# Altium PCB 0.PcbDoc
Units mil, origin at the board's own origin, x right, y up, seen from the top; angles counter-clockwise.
Board outline 2362.2 x 1889.76 mil, 2 copper layers (Top Layer, Bottom Layer); 26 components, 34 nets, 135 pads, 53 vias.
Unrouted connection lines stored in the file: 52.
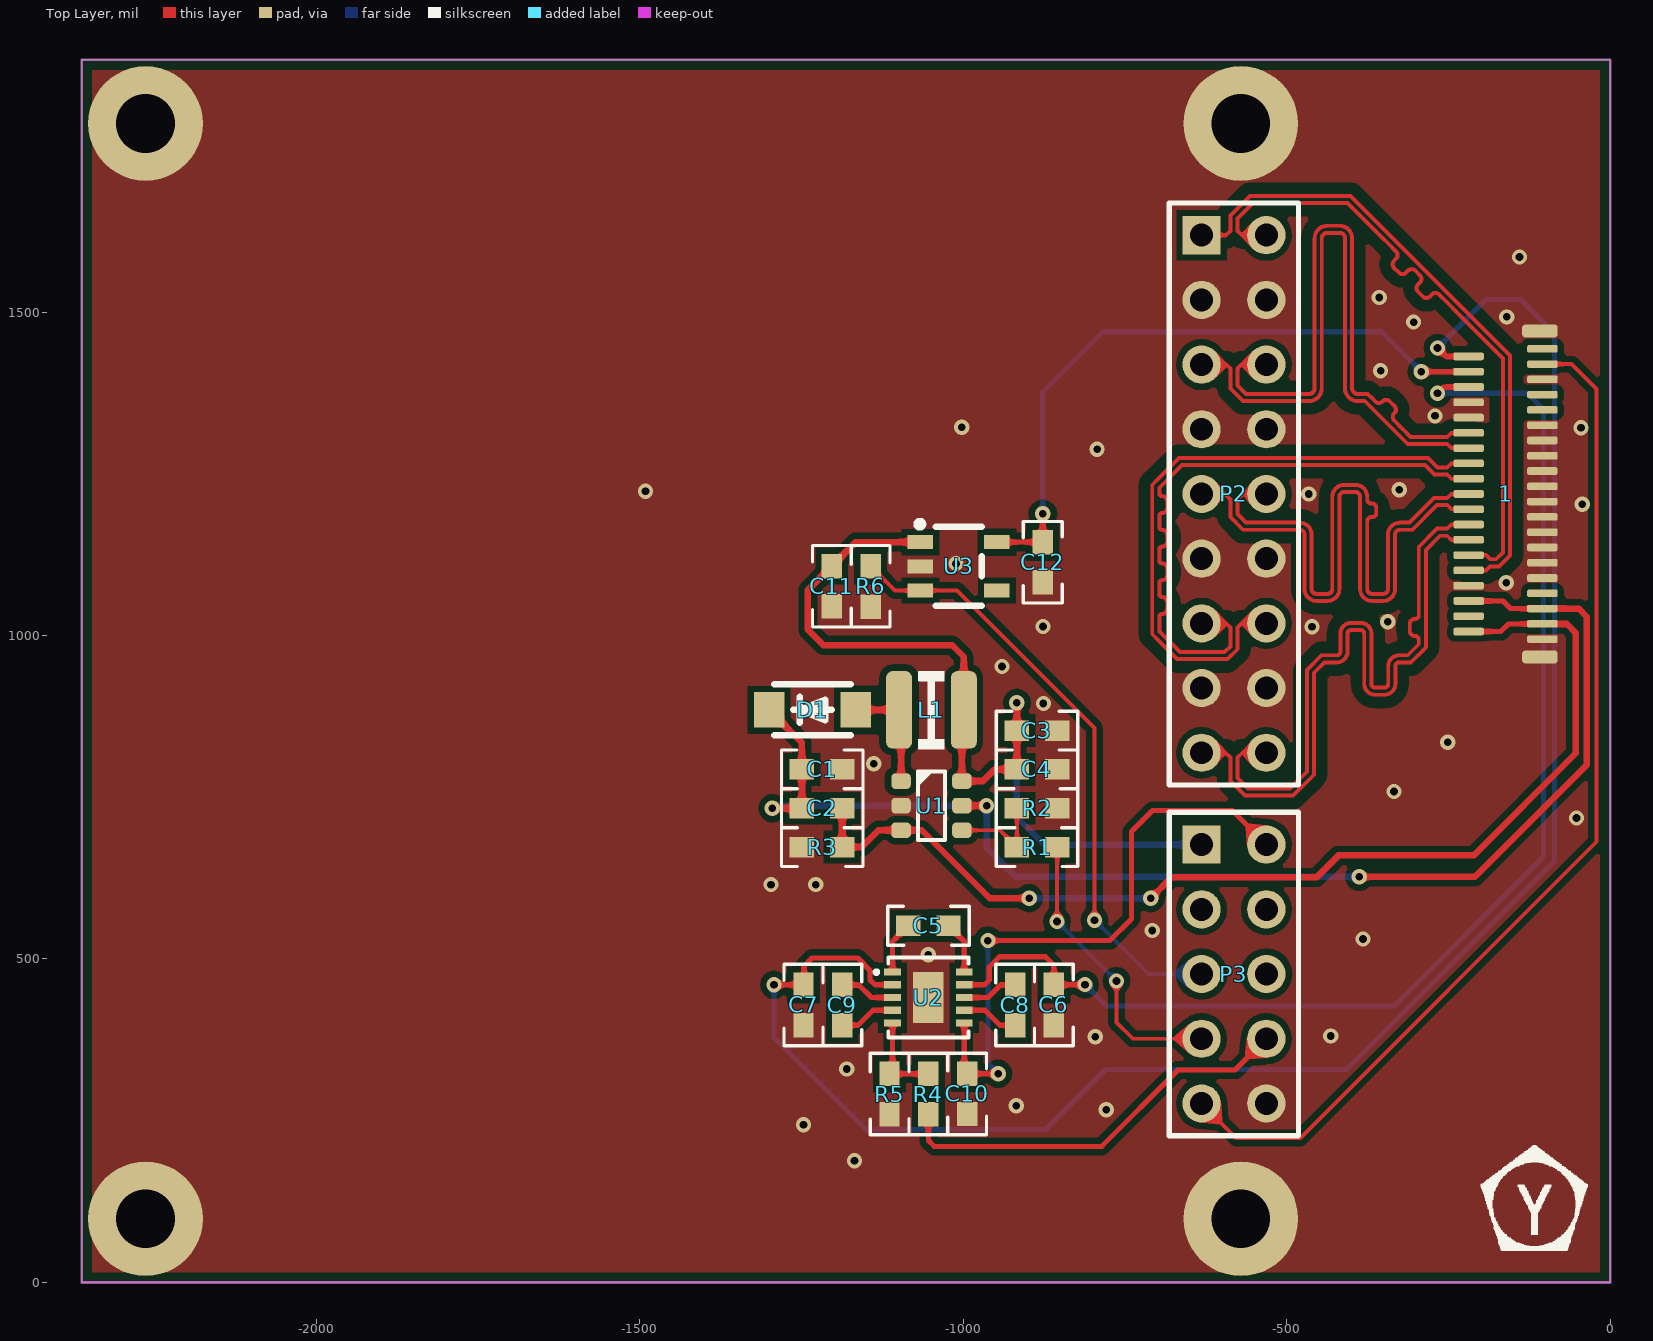
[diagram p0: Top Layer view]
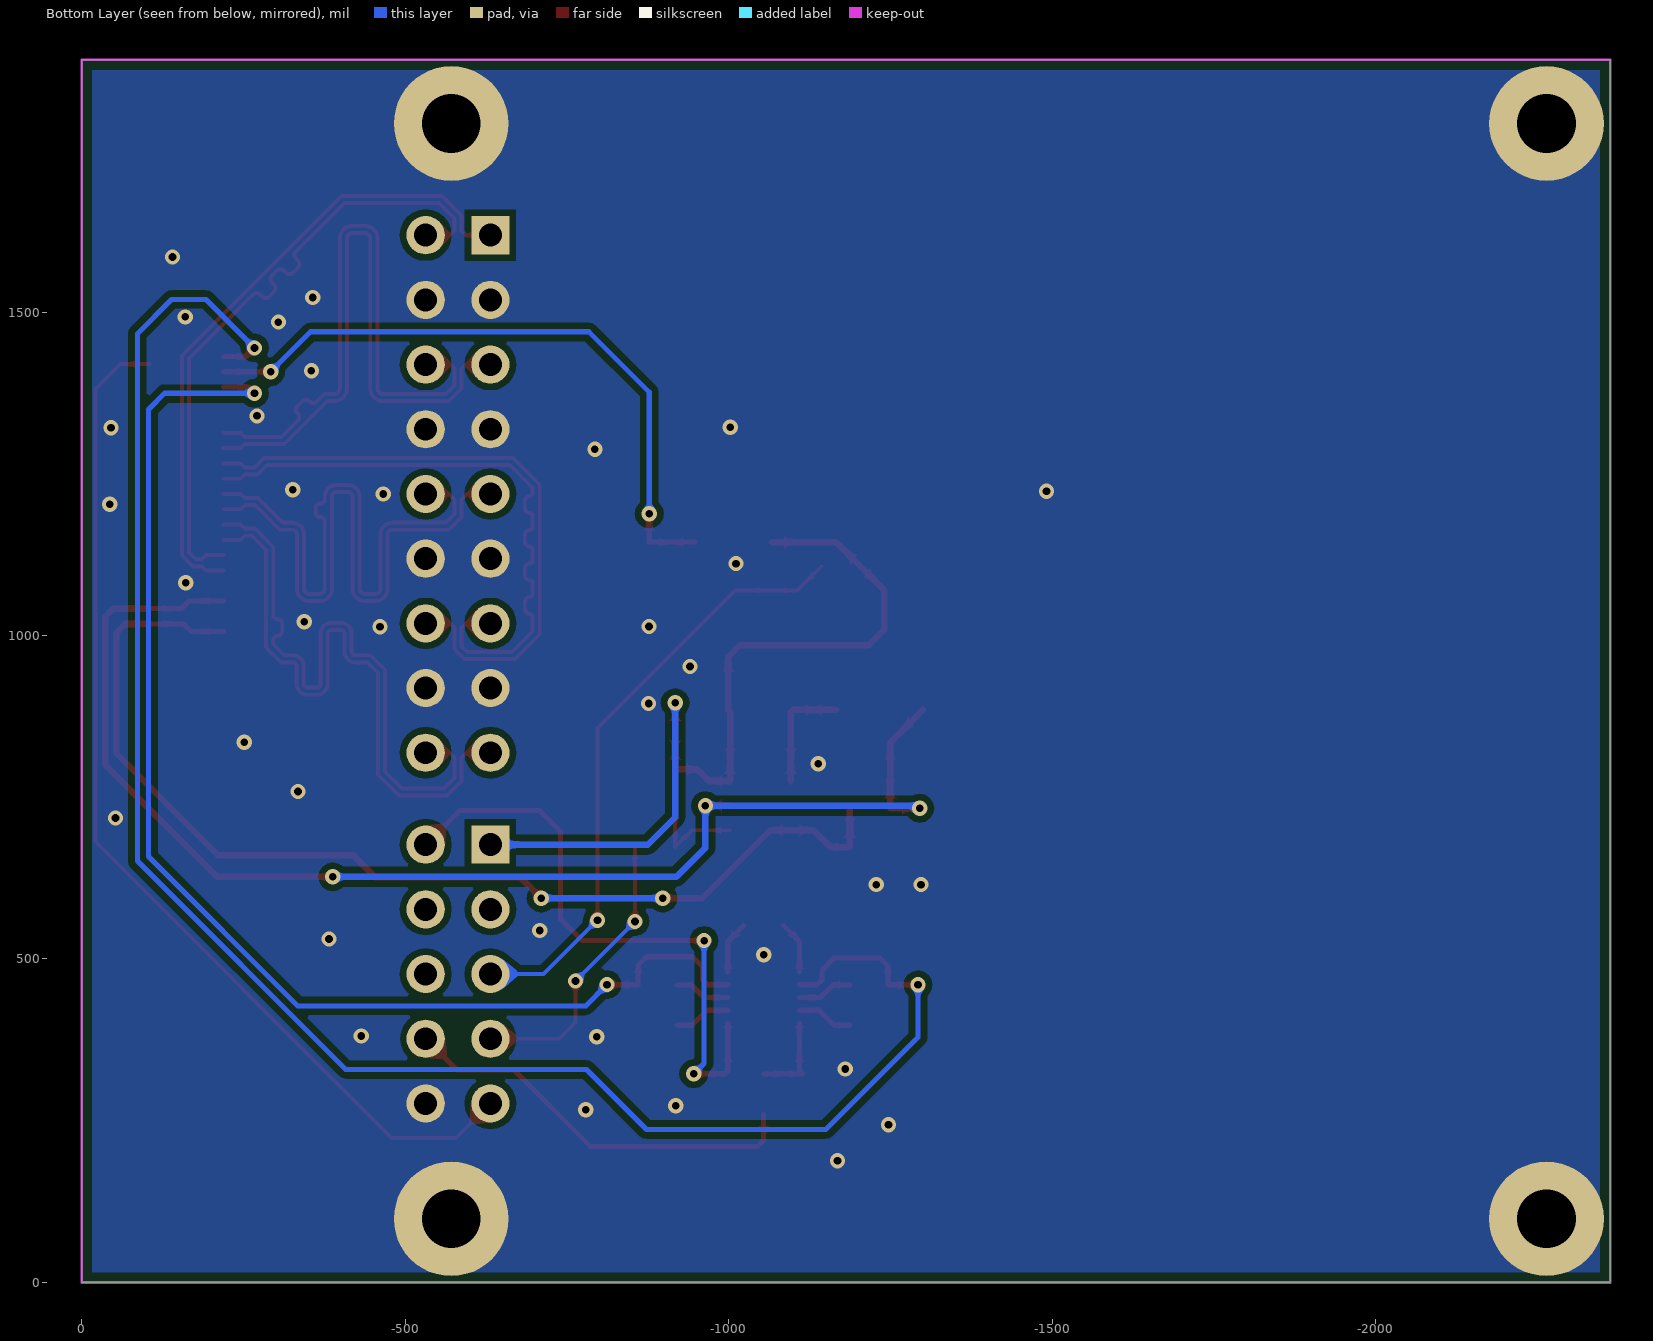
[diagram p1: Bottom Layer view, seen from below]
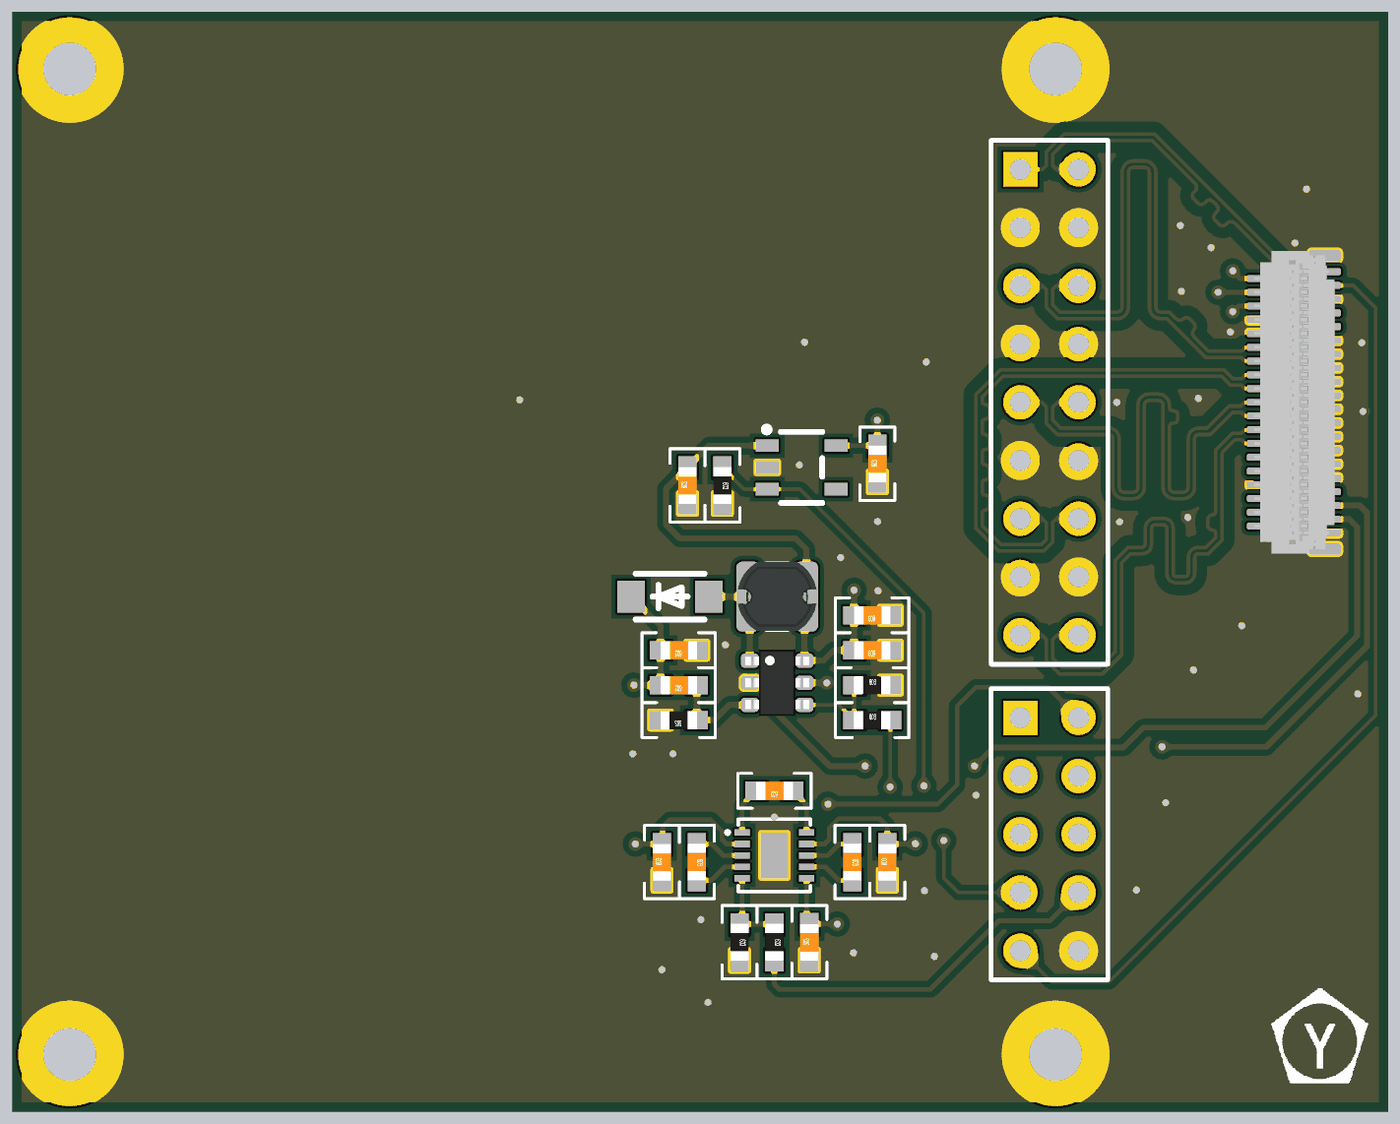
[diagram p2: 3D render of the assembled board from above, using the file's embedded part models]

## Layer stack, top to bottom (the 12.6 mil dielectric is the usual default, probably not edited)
Top Solder: solder mask 0.4, Solder Resist, Dk 3.5
Top Layer: signal copper 1.4
Dielectric 1: dielectric 12.6, FR-4, Dk 4.8
Bottom Layer: signal copper 1.4
Bottom Solder: solder mask 0.4, Solder Resist, Dk 3.5

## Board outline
-2362.2,0 -2362.2,1889.76 0,1889.76 0,0

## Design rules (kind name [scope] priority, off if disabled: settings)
BoardOutlineClearance [All] p1: gap=15.75 ignorepadtopadclearanceinfootprint=FALSE
Clearance Clearance_1 [(InDifferentialPairClass('All Differential Pairs')) vs InPolygon] p1: gap=10 ignorepadtopadclearanceinfootprint=FALSE except(18: Arc-Arc Arc-Track Arc-Fill Arc-Poly Arc-Region Track-Track Track-Fill Track-Poly Track-Region)
Clearance Clearance_2 [InNamedPolygon('GND_L01_P001') Or  InNamedPolygon('GND_L02_P002')] p2: gap=10 ignorepadtopadclearanceinfootprint=FALSE except(0: Arc-Hole Track-Hole SMDPad-Hole THPad-Hole Via-Hole Fill-Hole Poly-Hole Region-Hole Text-Hole)
Clearance [All] p3: gap=5 ignorepadtopadclearanceinfootprint=FALSE
DiffPairsRouting MIPI_DiffPairsRouting [InDifferentialPair ('MIPI0_D1') Or InDifferentialPair ('MIPI0_D3') Or InDifferentialPair ('MIPI0_D2') Or InDifferentialPair ('MIPI0_DC') Or InDifferentialPair ('MIPI0_D0')] p1: maxlimit=5 minlimit=5 mostfreqgap=5 toplayer_minwidth=6 toplayer_maxwidth=6 toplayer_prefwidth=6 bottomlayer_minwidth=6 bottomlayer_maxwidth=6 bottomlayer_prefwidth=6 maxuncoupledlength=500
DiffPairsRouting [All] p2: maxlimit=10 minlimit=10 mostfreqgap=10 toplayer_minwidth=15 toplayer_maxwidth=15 toplayer_prefwidth=15 bottomlayer_minwidth=15 bottomlayer_maxwidth=15 bottomlayer_prefwidth=15 maxuncoupledlength=500
MatchedLengths MIPI_MatchedLengths [InDifferentialPair ('MIPI0_D1') Or InDifferentialPair ('MIPI0_D3') Or InDifferentialPair ('MIPI0_D2') Or InDifferentialPair ('MIPI0_DC') Or InDifferentialPair ('MIPI0_D0')] p1: tolerance=21 checknetsindiffpair=FALSE checkdiffpairvsdiffpair=TRUE checkxsignals=TRUE checkothers=TRUE
MinimumSolderMaskSliver [All] p1: minsoldermaskwidth=0.1
PolygonConnect [All] p1: connectstyle=Direct reliefconductorwidth=10 reliefentries=4 polygonreliefangle="90 Angle" airgapwidth=10
RoutingVias [All] p1: holewidth=28 width=50 viastyle="Through Hole" minholewidth=28 minwidth=50 maxholewidth=28 maxwidth=50
SilkToSilkClearance [All] p1: silktosilkclearance=0
SilkToSolderMaskClearance [IsPad] p1: minsilkscreentomaskgap=0 clearancetoexposedcopper=TRUE
SolderMaskExpansion [All] p1: expansion=4
Width [All] p1: maxlimit=100 minlimit=1 preferedwidth=6 minimp=50.000000 maximp=50.000000 favimp=50.000000
26 further rules are at their usual default settings.

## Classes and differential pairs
differential pair MIPI0_DC: +MIPI0_DC_P -MIPI0_DC_N
differential pair MIPI0_D3: +MIPI0_D3_P -MIPI0_D3_N
differential pair MIPI0_D2: +MIPI0_D2_P -MIPI0_D2_N
differential pair MIPI0_D1: +MIPI0_D1_P -MIPI0_D1_N
differential pair MIPI0_D0: +MIPI0_D0_P -MIPI0_D0_N

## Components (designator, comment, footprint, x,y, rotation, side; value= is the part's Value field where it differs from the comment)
1 "FH26-39S-0.3SHW" FH26-39S-0.3SHW -218.78,1218.76 r90 top
C1 "2.2uf" 0603_CAP -1218.1,793 r180 top value=0.1u
C2 "2.2uf" 0603_CAP -1218.1,733 r180 top value=0.1u
C3 "10uf" 0603_CAP -885.9,853 r180 top value=0.1u
C4 "0.1uf" 0603_CAP -885.9,793 r180 top value=0.1u
C5 "2.2uf" 0603_CAP -1053.78,551.43 r180 top value=0.1u
C6 "10uf" 0603_CAP -859.78,429.01 r90 top value=0.1u
C7 "10uf" 0603_CAP -1246.78,429.01 r90 top value=0.1u
C8 "2.2uf" 0603_CAP -919.78,428.8 r270 top value=0.1u
C9 "2.2uf" 0603_CAP -1186.78,428.8 r270 top value=0.1u
C10 "10uf" 0603_CAP -993.78,291.53 r90 top value=0.1u
C11 "10uf" 0603_CAP -1203,1076.1 r90 top value=0.1u
C12 "10uf" 0603_CAP -877,1113.3 r90 top value=0.1u
D1 "RSX501L-20" SOD-123F_L2.8-W1.8-LS3.7-RD -1232.93,885 r0 top
L1 "CD32" IND_CD32 -1049,885 r180 top value=22uH
P2 "Header 9X2" HDR2X9 -631.44,1618.76 r270 top
P3 "Header 5X2" HDR2X5 -631.44,676.76 r270 top
R1 "10K" 0603_RES -885.78,673 r0 top value=22R
R2 "100K" 0603_RES -885.78,733 r0 top value=22R
R3 "10R" 0603_RES -1218.1,673 r180 top value=22R
R4 "10K" 0603_RES -1053.78,291.32 r270 top value=22R
R5 "100K" 0603_RES -1113.78,291.32 r270 top value=22R
R6 "100K" 0603_RES -1143,1075.9 r270 top value=22R
U1 "RT9293" SOT23-6 -1049,737 r0 top
U2 "LP3102QVF" TDFN-10_L3.0-W3.0-P0.50-BL-EP -1053.78,440.43 r270 top
U3 "WL2803E18-5/TR" SOT-23-5_L3.0-W1.7-P0.95-LS2.8-TL -1007,1107 r0 top

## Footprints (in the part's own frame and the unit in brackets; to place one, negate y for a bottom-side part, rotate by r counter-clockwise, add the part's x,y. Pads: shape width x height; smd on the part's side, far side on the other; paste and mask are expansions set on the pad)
0603_CAP [mm]
  rect 0.96x0.8 smd: 1(-0.79,0) 2(0.79,0)
  silkscreen extent -1.6,-0.76 1.6,0.76, body extent -0.81,-0.4 0.79,0.4, height 0.3
0603_RES [mm]
  rect 0.96x0.8 smd: 1(-0.79,0) 2(0.79,0)
  silkscreen extent -1.6,-0.76 1.6,0.76, body extent -0.8,-0.4 0.8,0.4, height 0.3
FH26-39S-0.3SHW [mm]
  rrect50% 0.3x1.2 smd: 1(5.7,-2.9) 2(5.4,0) 3(5.1,-2.9) 4(4.8,0) 5(4.5,-2.9) 6(4.2,0) 7(3.9,-2.9) 8(3.6,0) 9(3.3,-2.9) 10(3,0) 11(2.7,-2.9) 12(2.4,0) 13(2.1,-2.9) 14(1.8,0) 15(1.5,-2.9) 16(1.2,0) 17(0.9,-2.9) 18(0.6,0) 19(0.3,-2.9) 20(0,0) 21(-0.3,-2.9) 22(-0.6,0) 23(-0.9,-2.9) 24(-1.2,0) 25(-1.5,-2.9) 26(-1.8,0) 27(-2.1,-2.9) 28(-2.4,0) 29(-2.7,-2.9) 30(-3,0) 31(-3.3,-2.9) 32(-3.6,0) 33(-3.9,-2.9) 34(-4.2,0) 35(-4.5,-2.9) 36(-4.8,0) 37(-5.1,-2.9) 38(-5.4,0) 39(-5.7,-2.9)
  rrect50% 0.5x1.4 smd: GND1(6.4,-2.8) GND2(-6.4,-2.8)
  body extent -6.6,-3.23 6.6,0.27, height 0.98
HDR2X5 [mm] "Connector; Header; 5x2 Position"
  rect 1.5x1.5 hole 0.9: 1(0,0)
  round 1.5 hole 0.9: 2(0,2.54) 3(2.54,0) 4(2.54,2.54) 5(5.08,0) 6(5.08,2.54) 7(7.62,0) 8(7.62,2.54) 9(10.16,0) 10(10.16,2.54)
  silkscreen extent -1.27,-1.27 11.43,3.81
HDR2X9 [mm] "Connector; Header; 9x2 Position"
  rect 1.5x1.5 hole 0.9: 1(0,0)
  round 1.5 hole 0.9: 2(0,2.54) 3(2.54,0) 4(2.54,2.54) 5(5.08,0) 6(5.08,2.54) 7(7.62,0) 8(7.62,2.54) 9(10.16,0) 10(10.16,2.54) 11(12.7,0) 12(12.7,2.54) 13(15.24,0) 14(15.24,2.54) 15(17.78,0) 16(17.78,2.54) 17(20.32,0) 18(20.32,2.54)
  silkscreen extent -1.27,-1.27 21.59,3.81
IND_CD32 [mil]
  rrect50% 40x120 smd: 1(-50,0) 2(50,0)
  silkscreen extent -20,-60 20,60, body extent -68,-59 68,59, height 83
SOD-123F_L2.8-W1.8-LS3.7-RD [mm]
  rect 1.2x1.4 smd: 1(-1.7,0) 2(1.7,0)
  silkscreen extent -1.5,-1 1.5,1
SOT23-6 [mil]
  rrect50% 30x24 smd: 1(-47,38) 2(-47,0) 3(-47,-38) 4(47,-38) 5(47,0) 6(47,38)
  silkscreen extent -21,-53 21,53, body extent -55,-57 55,57, height 57
SOT-23-5_L3.0-W1.7-P0.95-LS2.8-TL [mm]
  rect 1x0.55 smd: 1(-1.5,0.95) 2(-1.5,0) 3(-1.5,-0.95) 4(1.5,-0.95) 5(1.5,0.95)
  silkscreen extent -1.65,-1.55 0.9,1.78
TDFN-10_L3.0-W3.0-P0.50-BL-EP [mm]
  rect 0.28x0.665 smd: 1(-1,-1.407) 2(-0.5,-1.407) 3(0,-1.407) 4(0.5,-1.407) 5(1,-1.407) 6(1,1.407) 7(0.5,1.407) 8(0,1.407) 9(-0.5,1.407) 10(-1,1.407)
  rect 2x1.2 smd: 11(0,0)
  silkscreen extent -1.58,-2.11 1.58,1.58

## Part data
1: "39 Position FPC Connector Contacts, Bottom 0.012 _0.30mm_ Surface Mount, Right Angle", Package=None
C1 C2 C3 C4 C5 C6 C7 C8 C9 C10 C11 C12: library part 电容-0402, "Capacitor"
D1: "Diode Schottky 40V 1A Surface Mount SMA _DO-214AC_", Package="DO-214AC-214 ON Semiconductor"
L1: library part Ind_CD32, "Inductor"
P2: "Header, 9-Pin, Dual row"
P3: "Header, 5-Pin, Dual row"
R1 R2 R3 R4 R5 R6: library part 电阻-0402, "Resistor"
U1: "LCD-LED Driver"
U2: BOM_JLCPCB SMD=Yes, BOM_Manufacturer=LOWPOWER
U3: BOM_Manufacturer="WILLSEMI(Will Semicon)"

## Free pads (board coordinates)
  round 177.17 hole 90.55: 0(-2263.78,98.43) 0(-2263.78,1791.34) 0(-570.87,98.43) 0(-570.87,1791.34)

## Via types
v1: diameter 23.62, hole 11.81, Top Layer to Bottom Layer, tented both sides, 53 vias

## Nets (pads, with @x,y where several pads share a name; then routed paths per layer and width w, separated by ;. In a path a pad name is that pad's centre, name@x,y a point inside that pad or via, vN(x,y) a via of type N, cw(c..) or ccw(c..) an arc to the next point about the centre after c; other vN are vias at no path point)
GND: 1.5 1.8 1.10 1.11 1.13 1.15 1.17 1.19 1.21 1.23 1.25 1.27 1.29 1.31 1.32 1.39 1.GND1 1.GND2 C1.1 C3.1 C4.1 C6.1 C7.1 C10.1 C11.1 C12.1 P2.3 P2.4 P2.7 P2.8 P2.11 P2.12 P2.15 P2.16 P3.10 pad.0 R2.2 R3.2 R5.2 R6.2 U1.2 U2.11 U3.2
  other v1: -1168,188 -1246.78,244 -779,267 -918,273 -1180,330 -796,380 -432,381 -1053.78,506.43 -382,531 -707.57,544 -1297,615 -1228,615 -52,718 -334,759 -1138,802 -251,835 -876,895 -940,952 -876.58,1014 -460.78,1013.43 -343.9,1021.1 -160.78,1081.43 -1011,1111.14 -43,1203 -465.78,1218.76 -1491,1223 -325.78,1225.43 -793,1288 -45,1321 -1002,1322 -270.78,1339.43 -354.78,1409.43 -303.78,1484.43 -159.78,1492.43 -356.78,1522.43 -140,1585
MIPI0_D0_N: 1.26 P2.17 | length 982.3
  Top Layer w6: P2.17 -594.28,818.76 -586.94,811.43 -586.94,775.03 -567.56,755.65 -564.34,752.43 -490.22,752.43 -487,755.65 -461,781.65 -457.78,784.87 -457.78,942.43 -441.78,958.43 -422.6,958.43 ccw(c-422.6,975.03) -406,975.03 -406,1002.83 cw(c-400.4,1002.83) -400.4,1008.43 -385.6,1008.43 cw(c-385.6,1002.83) -380,1002.83 -380,925.03 ccw(c-363.4,925.03) -363.4,908.43 -348.6,908.43 ccw(c-348.6,925.03) -332,925.03 -332,952.83 cw(c-326.4,952.83) -326.4,958.43 -308.22,958.43 -288,978.65 -284.78,981.87 -284.78,1132.21 -262.78,1154.21 -251.71,1154.21 -245.4,1147.9 1.26
MIPI0_D0_P: 1.24 P2.18 | length 980
  Top Layer w6: P2.18 -568.6,818.76 -575.94,811.43 -575.94,779.59 -559.78,763.43 -494.78,763.43 -468.78,789.43 -468.78,946.98 -446.34,969.43 -422.6,969.43 ccw(c-422.6,975.03) -417,975.03 -417,1002.83 cw(c-400.4,1002.83) -400.4,1019.43 -385.6,1019.43 cw(c-385.6,1002.83) -369,1002.83 -369,925.03 ccw(c-363.4,925.03) -363.4,919.43 -348.6,919.43 ccw(c-348.6,925.03) -343,925.03 -343,952.83 cw(c-326.4,952.83) -326.4,969.43 -312.78,969.43 -295.78,986.43 -295.78,993.23 ccw(c-301.98,993.23) -301.98,999.43 cw(c-301.98,1007.23) -309.78,1007.23 -309.78,1017.63 cw(c-301.98,1017.63) -301.98,1025.43 ccw(c-301.98,1031.63) -295.78,1031.63 -295.78,1051.43 -295.78,1062.43 -295.78,1136.77 -267.34,1165.21 -251.71,1165.21 -245.4,1171.52 1.24
MIPI0_D1_N: 1.18 P2.13 | length 982
  Top Layer w6: P2.13 -593.28,1018.76 -586.94,1012.43 -586.94,983.26 -595.78,974.43 -664.78,974.43 -696.78,1006.43 -696.78,1007.43 -696.78,1029.03 cw(c-692.38,1029.03) -692.38,1033.43 ccw(c-692.38,1041.23) -684.58,1041.23 -684.58,1051.63 ccw(c-692.38,1051.63) -692.38,1059.43 cw(c-692.38,1063.83) -696.78,1063.83 -696.78,1081.03 cw(c-692.38,1081.03) -692.38,1085.43 ccw(c-692.38,1093.23) -684.58,1093.23 -684.58,1103.63 ccw(c-692.38,1103.63) -692.38,1111.43 cw(c-692.38,1115.83) -696.78,1115.83 -696.78,1133.03 cw(c-692.38,1133.03) -692.38,1137.43 ccw(c-692.38,1145.23) -684.58,1145.23 -684.58,1155.63 ccw(c-692.38,1155.63) -692.38,1163.43 cw(c-692.38,1167.83) -696.78,1167.83 -696.78,1185.03 cw(c-692.38,1185.03) -692.38,1189.43 ccw(c-692.38,1197.23) -684.58,1197.23 -684.58,1207.63 ccw(c-692.38,1207.63) -692.38,1215.43 cw(c-692.38,1219.83) -696.78,1219.83 -696.78,1228.43 -661.78,1263.43 -286.06,1263.43 -271.34,1248.7 -251.71,1248.7 -245.4,1242.39 1.18
MIPI0_D1_P: 1.16 P2.14 | length 980.9
  Top Layer w6: P2.14 -569.6,1018.76 -575.94,1012.43 -575.94,978.71 -591.22,963.43 -669.34,963.43 -697.56,991.65 -707.78,1001.87 -707.78,1232.98 -697.56,1243.2 -666.34,1274.43 -281.51,1274.43 -266.78,1259.7 -251.71,1259.7 -245.4,1266.01 1.16
MIPI0_D2_N: 1.14 P2.5 | length 979.7
  Top Layer w6: P2.5 -593.28,1418.76 -586.94,1412.43 -586.94,1382.03 -567.34,1362.43 -465.38,1362.43 ccw(c-465.38,1382.03) -445.78,1382.03 -445.78,1613.83 cw(c-437.18,1613.83) -437.18,1622.43 -418.38,1622.43 cw(c-418.38,1613.83) -409.78,1613.83 -409.78,1382.03 ccw(c-390.18,1382.03) -390.18,1362.43 -379.34,1362.43 -312.85,1295.94 -251.71,1295.94 -245.4,1289.63 1.14
MIPI0_D2_P: 1.12 P2.6 | length 980.1
  Top Layer w6: P2.6 -569.6,1418.76 -575.94,1412.43 -575.94,1386.59 -562.78,1373.43 -465.38,1373.43 ccw(c-465.38,1382.03) -456.78,1382.03 -456.78,1613.83 cw(c-437.18,1613.83) -437.18,1633.43 -418.38,1633.43 cw(c-418.38,1613.83) -398.78,1613.83 -398.78,1382.03 ccw(c-390.18,1382.03) -390.18,1373.43 -374.78,1373.43 -366.78,1365.43 -363.1,1361.75 ccw(c-357.59,1367.26) -352.07,1361.75 -351.79,1362.03 cw(c-346.27,1356.52) -340.76,1362.03 -333.4,1354.68 cw(c-338.92,1349.16) -333.4,1343.65 -333.69,1343.36 ccw(c-328.17,1337.85) -333.69,1332.33 -320.82,1319.46 -319.78,1318.43 -308.3,1306.94 -251.71,1306.94 -245.4,1313.25 1.12
MIPI0_D3_N: 1.30 P2.1 | length 1000.6
  Top Layer w6: P2.1 -593.6,1618.76 -586.94,1625.43 -586.94,1649.26 -556.78,1679.43 -401.22,1679.43 -154.78,1432.98 -154.78,1123.72 -171.53,1106.96 -185.85,1106.96 -192.16,1100.65 1.30
MIPI0_D3_P: 1.28 P2.2 | length 999.2
  Top Layer w6: P2.2 -569.28,1618.76 -575.94,1625.43 -575.94,1644.71 -552.22,1668.43 -405.78,1668.43 -352.78,1615.43 -343.59,1606.23 -330.72,1593.36 cw(c-336.23,1587.85) -330.72,1582.33 -333.83,1579.22 ccw(c-328.31,1573.71) -333.83,1568.19 -326.48,1560.84 ccw(c-320.96,1566.35) -315.44,1560.84 -312.33,1563.95 cw(c-306.82,1558.43) -301.3,1563.95 -293.95,1556.59 cw(c-299.46,1551.08) -293.95,1545.56 -297.06,1542.45 ccw(c-291.54,1536.94) -297.06,1531.42 -289.71,1524.07 ccw(c-284.19,1529.58) -278.67,1524.07 -275.56,1527.18 cw(c-270.05,1521.66) -264.53,1527.18 -251.66,1514.31 -235.78,1498.43 -165.78,1428.43 -165.78,1128.28 -176.09,1117.96 -185.85,1117.96 -192.16,1124.28 1.28
MIPI0_DC_N: 1.22 P2.9 | length 982.7
  Top Layer w6: P2.9 -595.28,1218.76 -586.94,1210.43 -586.94,1183.03 -567.34,1163.43 -479.85,1163.43 cw(c-479.85,1156.03) -472.45,1156.03 -472.45,1071.83 ccw(c-454.05,1071.83) -454.05,1053.43 -436.85,1053.43 ccw(c-436.85,1071.83) -418.45,1071.83 -418.45,1214.53 cw(c-411.05,1214.53) -411.05,1221.93 -393.85,1221.93 cw(c-393.85,1214.53) -386.45,1214.53 -386.45,1071.83 ccw(c-368.05,1071.83) -368.05,1053.43 -350.85,1053.43 ccw(c-350.85,1071.83) -332.45,1071.83 -332.45,1156.03 cw(c-325.05,1156.03) -325.05,1163.43 -305.67,1163.43 -267.64,1201.45 -251.71,1201.45 -245.4,1195.14 1.22
MIPI0_DC_P: 1.20 P2.10 | length 981.7
  Top Layer w6: P2.10 -567.6,1218.76 -575.94,1210.43 -575.94,1187.59 -562.78,1174.43 -479.85,1174.43 cw(c-479.85,1156.03) -461.45,1156.03 -461.45,1071.83 ccw(c-454.05,1071.83) -454.05,1064.43 -436.85,1064.43 ccw(c-436.85,1071.83) -429.45,1071.83 -429.45,1214.53 cw(c-411.05,1214.53) -411.05,1232.93 -393.85,1232.93 cw(c-393.85,1214.53) -375.45,1214.53 -375.45,1210.33 ccw(c-369.15,1210.33) -369.15,1204.03 -367.75,1204.03 cw(c-367.75,1197.73) -361.45,1197.73 -361.45,1189.33 cw(c-367.75,1189.33) -367.75,1183.03 -369.15,1183.03 ccw(c-369.15,1176.73) -375.45,1176.73 -375.45,1162.03 -375.45,1154.43 -375.45,1071.83 ccw(c-368.05,1071.83) -368.05,1064.43 -350.85,1064.43 ccw(c-350.85,1071.83) -343.45,1071.83 -343.45,1156.03 cw(c-325.05,1156.03) -325.05,1174.43 -310.22,1174.43 -272.2,1212.45 -251.71,1212.45 -245.4,1218.76 1.20
NetC5_1: C5.1 U2.10 | length 81.7
  Top Layer w8: C5.1 -998.37,527.11 U2.10
NetC5_2: C5.2 U2.1 | length 81.7
  Top Layer w8: U2.1 -1109.19,527.11 C5.2
NetC8_1: C8.1 U2.8 | length 86.7
  Top Layer w8: U2.8 -961.78,440.43 -942.3,459.91 C8.1
NetC8_2: C8.2 U2.7 | length 88.1
  Top Layer w8: U2.7 -966.09,420.74 -943.06,397.7 C8.2
NetC9_1: C9.1 U2.3 | length 85.7
  Top Layer w8: C9.1 -1161.26,459.91 -1141.78,440.43 U2.3
NetC9_2: C9.2 U2.4 | length 87.1
  Top Layer w8: C9.2 -1162.5,397.7 -1139.46,420.74 U2.4
NetD1_2: D1.2 L1.2 U1.1 | length 178.2
  Top Layer w10: D1.2 L1.2 -1096,882 U1.1
NetR1_1: R1.1 R2.1 U1.4 | length 155.9
  Top Layer w6: U1.4 -942.88,699 R1.1 R2.1
NetR4_1: R4.1 R5.1 U2.5 | length 140.5
  Top Layer w8: U2.5 -1109.19,327.01 R5.1 R4.1
PA2: 1.3 P3.9 | length 1621.5
  Top Layer w6: P3.9 -578.1,223.43 -478.78,223.43 -21,681.2 -21,1380.96 -59.59,1419.55 1.3
PA3: P3.7 R1.2 | length 451.3
  Top Layer w6: v1(-855,558) -854.68,558.32 R1.2 ; v1(-763,466) -763,402 -737.76,376.76 P3.7
  Bottom Layer w6: v1(-855,558) v1(-763,466)
PA4: P3.8 R4.2 | length 635.8
  Top Layer w8: R4.2 -1053.78,219.43 -1044.78,210.43 -785.78,210.43 -667.78,328.43 -579.78,328.43 P3.8
PA6: P3.5 R6.1 U3.3 | length 946.6
  Top Layer w6: R6.1 -1105.6,1069.6 U3.3 -1009.6,1069.6 -797,857 v1(-797,560)
  Bottom Layer w6: v1(-797,560) -713.76,476.76 P3.5
PA7: P3.6
VCC_1V1: P3.4
VCC_1V8: P3.3
VCC_3V3: C10.2 P3.2 U2.6 | length 956.7
  Top Layer w8: U2.6 -998.37,327.22 C10.2 v1(-945.78,322.63) ; v1@-962.78,527.43 v1(-961.78,528.43) -773.57,528.43 -740,562 -740,697 -707.57,729.43 -584.1,729.43 P3.2
  Bottom Layer w8: v1(-961.78,528.43) -961.78,338.63 v1(-945.78,322.63)
VDDI: 1.4 C12.2 U3.5 | length 1025
  Top Layer w8: U3.5 C12.2 ; v1(-291.78,1407.74) 1.4
  Top Layer w9: C12.2 v1(-877,1188)
  Bottom Layer w8: v1(-877,1188) -877,1376 -783.57,1469.43 -353.46,1469.43 v1(-291.78,1407.74)
VLED+: 1.34 1.35 C1.2 C2.2 D1.1 U1.5 | length 2095
  Top Layer w8: 1.34 -165.59,1053.41 -153.78,1041.6 1.35
  Top Layer w10: D1.1 -1249.2,834.34 C1.2 C2.2 v1(-1295,733) ; U1.5 v1(-963.78,737) ; v1(-388,627) -209,627 -36,800 -36,1029 -48.6,1041.6 1.35
  Bottom Layer w10: v1(-1295,733) -1291,737 v1(-963.78,737) -963.78,671.78 -919,627 v1(-388,627)
VLED-: 1.37 1.38 C2.1 R3.1 U1.3 | length 1703.5
  Top Layer w8: 1.38 -169.04,1006.17 -157.23,1017.98 1.37
  Top Layer w10: C2.1 R3.1 -1157,673 -1131,699 U1.3 -1064,699 -959,594 v1(-898,594) ; v1(-710,594) -678,626 -454,626 -420,660 -211,660 -53,818 -53,1004 -66.98,1017.98 1.37
  Bottom Layer w10: v1(-898,594) v1(-710,594)
VSN: 1.2 C7.2 U2.2 | length 2864.4
  Top Layer w8: v1@-1292.78,460.43 v1(-1292.46,460.11) C7.2 -1245.78,461.11 -1245.78,489.43 -1233.78,501.43 -1162.78,501.43 -1143.78,482.43 -1143.78,467.43 -1136.46,460.11 U2.2 ; v1(-266.78,1444.43) -253.72,1431.36 1.2
  Bottom Layer w8: v1(-1292.46,460.11) -1292.46,379.11 -1149.78,236.43 -872.78,236.43 -779.78,329.43 -407.78,329.43 -85.78,651.43 -85.78,1466.43 -138.78,1519.43 -191.78,1519.43 v1(-266.78,1444.43)
VSP: 1.6 C6.2 U2.9 | length 1987.8
  Top Layer w8: U2.9 -967.09,460.11 -959.78,467.43 -959.78,487.43 -943.78,503.43 -872.78,503.43 -859.78,490.43 C6.2 -812.09,460.11 v1(-811.78,460.43) ; v1(-266.78,1374.43) -257.09,1384.12 1.6
  Bottom Layer w8: v1(-811.78,460.43) -778.78,427.43 -333.78,427.43 -102.78,658.43 -102.78,1349.43 -127.78,1374.43 v1(-266.78,1374.43)
VUSB: C3.2 C4.2 C11.2 L1.1 P3.1 U1.6 U3.1 | length 1393
  Top Layer w10: U3.1 -1165.8,1144.4 C11.2 -1240,1070.2 -1240,1009 -1216,985 -1017,985 -999,967 L1.1 -1002,882 U1.6 -969.46,775 -951.46,793 C4.2 C3.2 v1(-917,896)
  Bottom Layer w10: v1(-917,896) -917,719 -874.76,676.76 P3.1
pads on no net: 1.1 1.7 1.9 1.33 1.36 U3.4

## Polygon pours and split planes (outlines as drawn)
GND on Bottom Layer "GND_L02_P002" (solid, remove dead copper, pour order 2): -2362.2,0 -2362.2,1889.76 0,1889.76 0,0
GND on Top Layer "GND_L01_P001" (solid, remove dead copper, pour order 1): -2362.2,0 -2362.2,1889.76 0,1889.76 0,0

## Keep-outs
Keep-Out Layer:
  the board outline again, w3.94

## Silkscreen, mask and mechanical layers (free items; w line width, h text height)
Top Overlay:
  drawing of 401 lines, arcs and shapes, not listed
